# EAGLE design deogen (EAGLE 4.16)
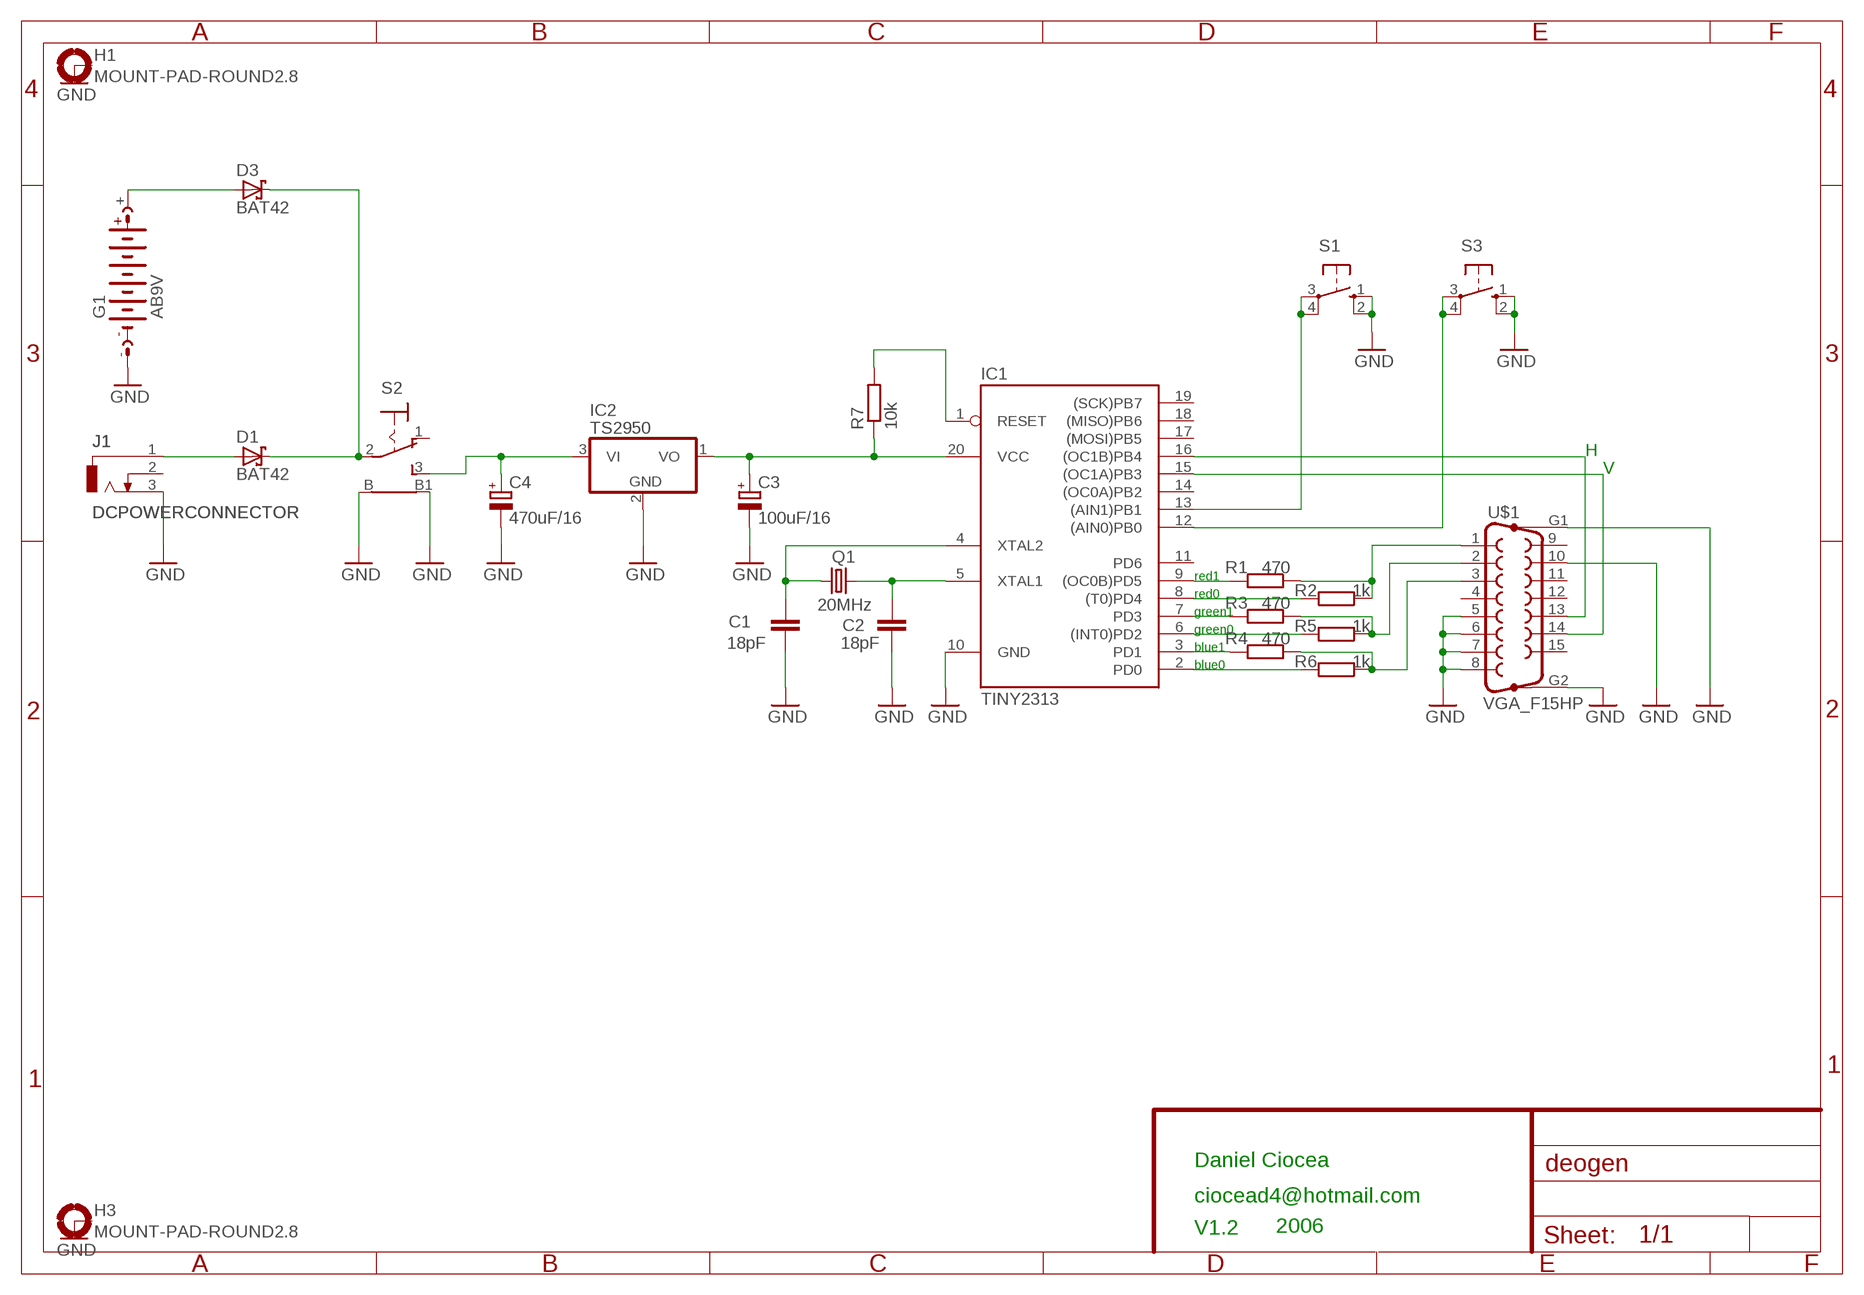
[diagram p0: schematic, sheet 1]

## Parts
C1  18pF  C-EU025-024X044  [C025-024X044]
C2  18pF  C-EU025-024X044  [C025-024X044]
C3  100uF/16  CPOL-EUE2.5-6  [E2,5-6]
C4  470uF/16  CPOL-EUE3.5-8  [E3,5-8]
D1  BAT42  [DO35-10]
D3  BAT42  [DO35-10]
G1  AB9V  [AB9V]
H1  MOUNT-PAD-ROUND2.8  [2,8-PAD]
H3  MOUNT-PAD-ROUND2.8  [2,8-PAD]
IC1  TINY2313  [DIL20]
IC2  TS2950  LINEAR_78L  [TO92]
J1  DCPOWERCONNECTOR  [DC_POWER_JACK]
Q1  20MHz  CRYTALHC49S  [HC49/S]
R1  470  R-EU_0207/7  [0207/7]
R2  1k  R-EU_0207/7  [0207/7]
R3  470  R-EU_0207/7  [0207/7]
R4  470  R-EU_0207/7  [0207/7]
R5  1k  R-EU_0207/7  [0207/7]
R6  1k  R-EU_0207/7  [0207/7]
R7  10k  R-EU_0207/7  [0207/7]
S1  10-XX  [B3F-10XX]
S2  9070-1W  [9070-1W]
S3  10-XX  [B3F-10XX]
U$1  VGA_F15HP  [F15]

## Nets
GND: C1.2 C2.2 C3.- C4.- G1.- H1.B2,8(MOUNT) H3.B2,8(MOUNT) IC1.10(GND) IC2.2(GND) J1.3 S1.1(S) S1.2(S1) S2.B S2.B1 S3.1(S) S3.2(S1) U$1.5 U$1.6 U$1.7 U$1.8 U$1.10 U$1.G1 U$1.G2
N$1: IC1.2(PD0) R6.2
N$2: IC1.3(PD1) R4.2
N$3: IC1.6((INT0)PD2) R5.2
N$4: IC1.7(PD3) R3.2
N$5: IC1.8((T0)PD4) R2.2
N$6: IC1.9((OC0B)PD5) R1.2
N$7: R1.1 R2.1 U$1.1
N$8: R3.1 R5.1 U$1.2
N$9: R4.1 R6.1 U$1.3
N$10: C1.1 IC1.4(XTAL2) Q1.1
N$11: C2.1 IC1.5(XTAL1) Q1.2
N$12: IC1.16((OC1B)PB4) U$1.13
N$13: IC1.15((OC1A)PB3) U$1.14
N$14: D1.C D3.C S2.2(P)
N$15: D1.A J1.1
N$16: IC1.13((AIN1)PB1) S1.3(P) S1.4(P1)
N$17: IC1.12((AIN0)PB0) S3.3(P) S3.4(P1)
N$19: IC1.1(RESET) R7.2
N$22: D3.A G1.+
N$23: C3.+ IC1.20(VCC) IC2.1(VO) R7.1
N$24: C4.+ IC2.3(VI) S2.3(S)
Unconnected: IC1.11(PD6) IC1.14((OC0A)PB2) IC1.17((MOSI)PB5) IC1.18((MISO)PB6) IC1.19((SCK)PB7) J1.2 S2.1(O) U$1.4 U$1.9 U$1.11 U$1.12 U$1.15

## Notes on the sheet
- H
- V
- red1
- red0
- green1
- green0
- blue1
- blue0
- Daniel Ciocea
- ciocead4@hotmail.com
- V1.2 | 2006

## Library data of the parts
C1 C2 = rcl:C-EU: CAPACITOR, European symbol
C3 C4 = rcl:CPOL-EU: POLARIZED CAPACITOR, European symbol
D1 D3 = diode:BAT42: DIODE
G1 = battery:AB9V: 9-V BATTERY CLIP
H1 H3 = holes:MOUNT-PAD-ROUND: MOUNTING PAD, round
IC1 = atmel:TINY2313*
IC2 = deogen:LINEAR_78*: Positive VOLTAGE REGULATOR Source: http://cache.national.com/ds/LM/LM78L05.pdf http://www.fairchildsemi.com/ds/LM/LM7805.pdf
J1 = deogen:DCPOWERCONNECTOR: DC POWER JACK Source: DCJ0202.pdf
Q1 = crystal:CRYTAL: CRYSTAL
R1-R7 = rcl:R-EU_: RESISTOR, European symbol
S1 S3 = switch-omron:10-XX: OMRON SWITCH
S2 = switch:9070-1W: TOGGLE SWITCH Marquardt
U$1 = deogen:VGA_F15HP

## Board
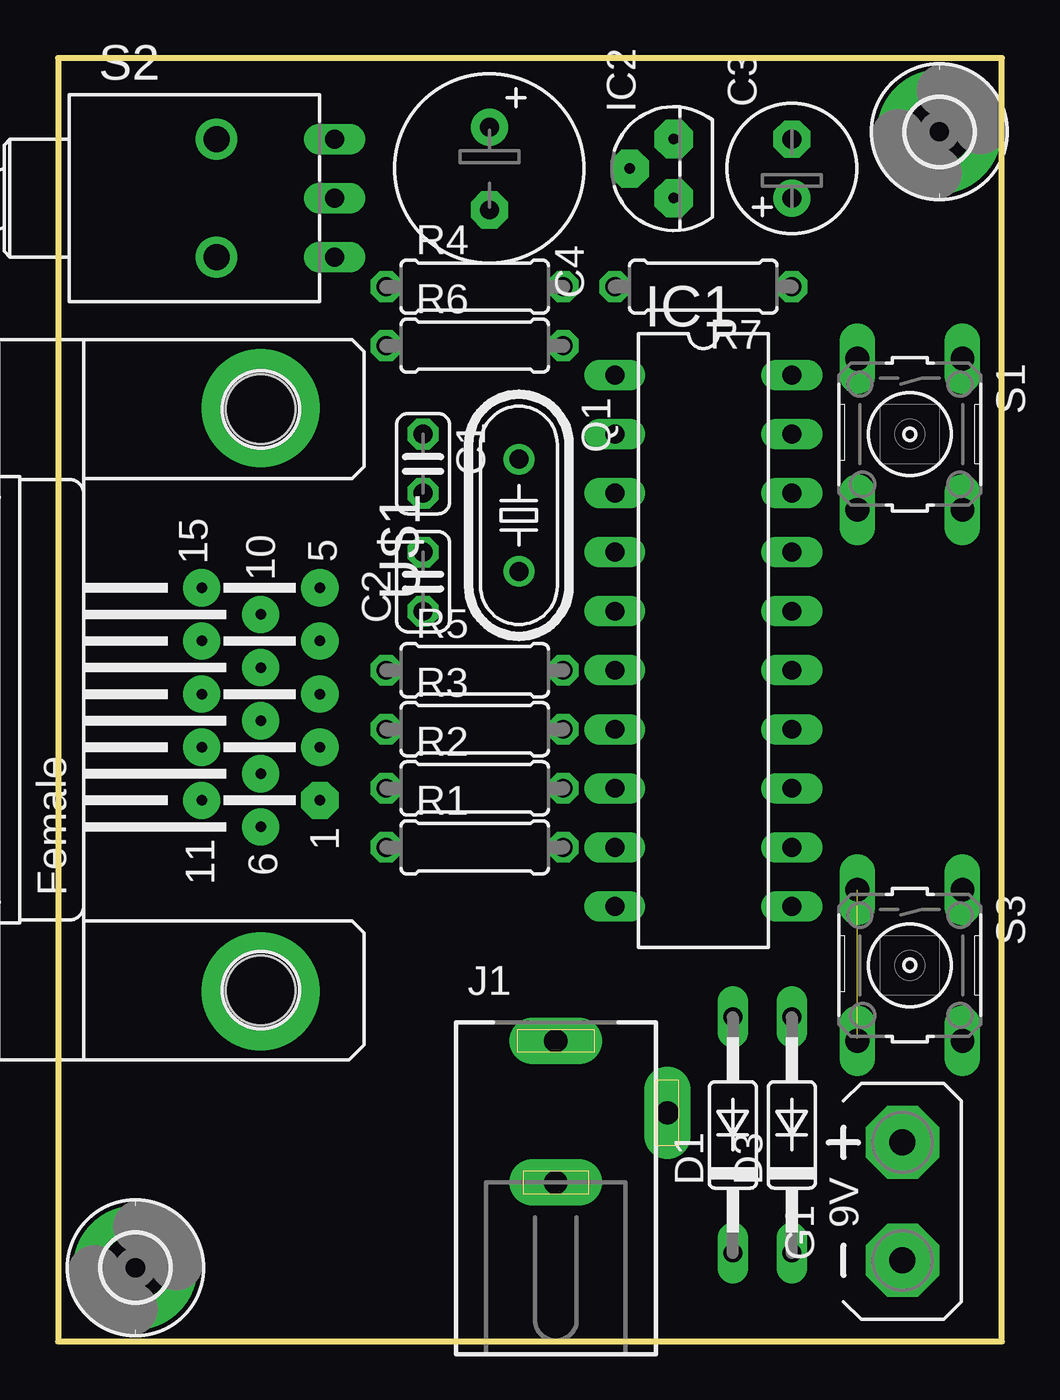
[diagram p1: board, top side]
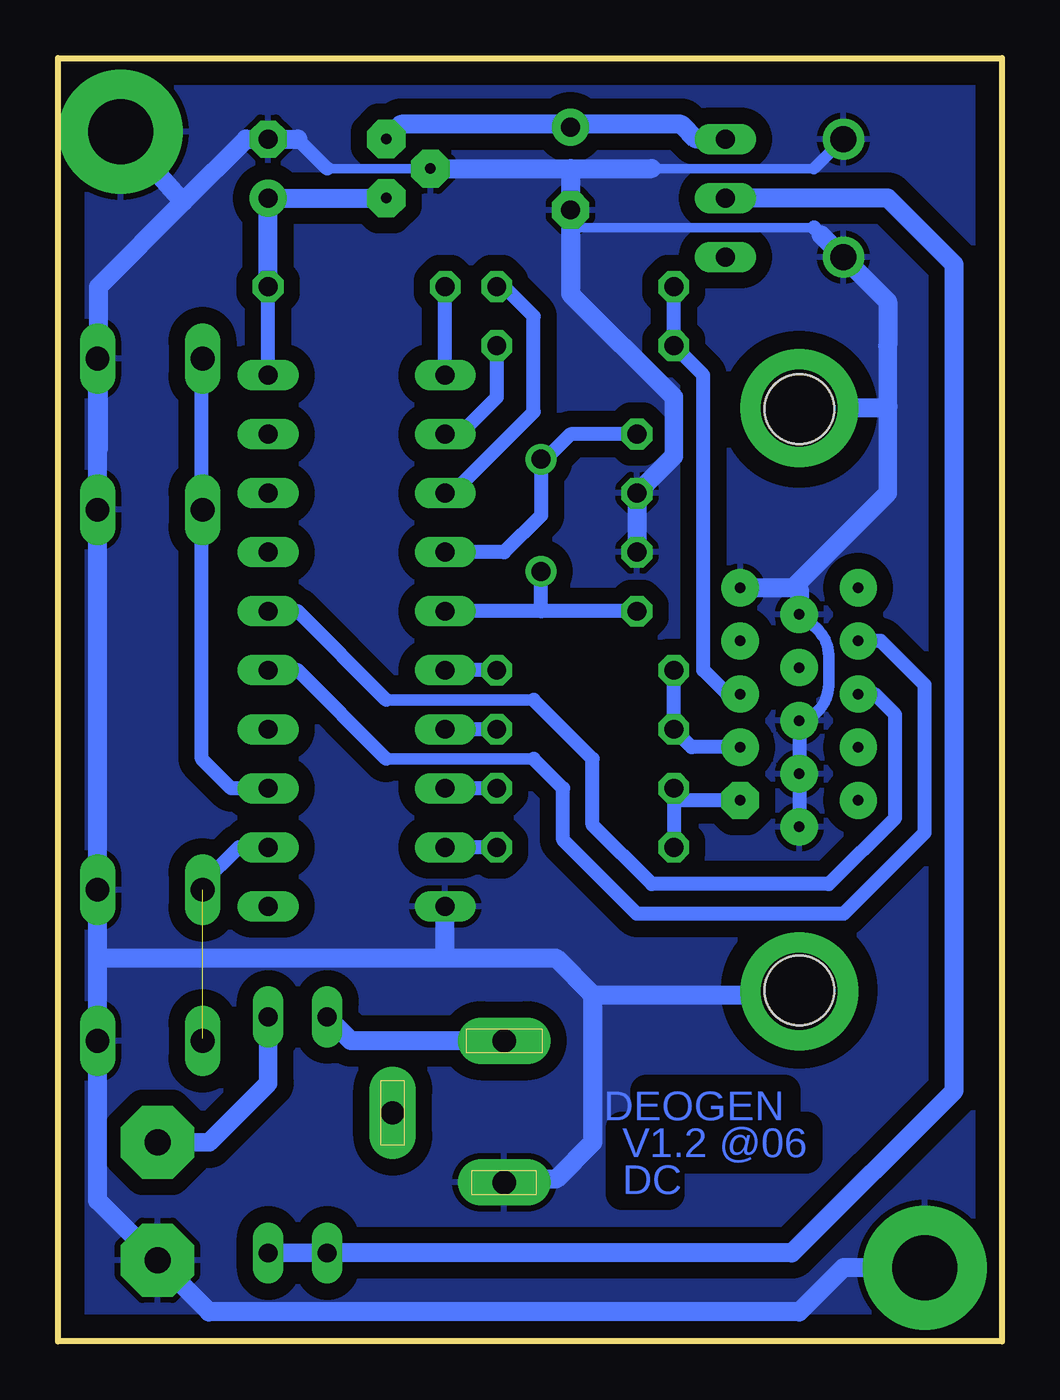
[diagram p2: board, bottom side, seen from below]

Size 40.63 x 55.23 mm. Coordinates in mm from the lower left corner, seen from the top.
Outline: 0,0 40.63,0 40.63,55.23 0,55.23 0,0
Copper layers (1*16): Top 0.035mm / dielectric 1.5mm / Bottom 0.035mm
Design rules "default": minimum track width 10mil, minimum drill 0.0102mm, track to track 8mil, track to pad 8mil, pad to pad 8mil, via to via 8mil, smd to smd 8mil, copper to edge 40mil, drill to drill 8mil, minimum pad ring 10mil, minimum via ring 8mil, stop-mask expansion 4mil, vias tented up to drill 0mil, thermal gap 10mil

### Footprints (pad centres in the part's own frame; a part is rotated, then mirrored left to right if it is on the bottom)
C025-024X044 = drill 0.813 octagon: 1 -1.27,0; 2 1.27,0
E2,5-6 = drill 0.813 pad 1.6 round: + -1.27,0 | drill 0.813 pad 1.6 octagon: - 1.27,0
E3,5-8 = drill 0.813 pad 1.6 round: + -1.778,0 | drill 0.813 pad 1.6 octagon: - 1.778,0
DO35-10 = drill 0.813 long: A 5.08,0; C -5.08,0
AB9V = drill 1.118 pad 3.15 octagon: + 0,2.54; - 0,-2.54
2,8-PAD = drill 2.8 pad 5.334 round: B2,8 0,0
DIL20 = drill 0.813 long: 1 -11.43,-3.81; 2 -8.89,-3.81; 3 -6.35,-3.81; 4 -3.81,-3.81; 5 -1.27,-3.81; 6 1.27,-3.81; 7 3.81,-3.81; 8 6.35,-3.81; 9 8.89,-3.81; 10 11.43,-3.81; 11 11.43,3.81; 12 8.89,3.81; 13 6.35,3.81; 14 3.81,3.81; 15 1.27,3.81; 16 -1.27,3.81; 17 -3.81,3.81; 18 -6.35,3.81; 19 -8.89,3.81; 20 -11.43,3.81
TO92 = drill 0.45 pad 1.65 octagon: 1 -1.27,0; 2 0,1.905; 3 1.27,0
DC_POWER_JACK = drill 1 pad 2 long: 1 0,3.1; 2 4.8,0; 3 0,-3
HC49/S = drill 0.813 round: 1 -2.413,0; 2 2.413,0
0207/7 = drill 0.813 octagon: 1 -3.81,0; 2 3.81,0
B3F-10XX = drill 1.016 long: 1 -3.251,2.261; 2 3.251,2.261; 3 -3.251,-2.261; 4 3.251,-2.261
9070-1W = drill 0.813 long: 1 5.08,-2.54; 2 5.08,0; 3 5.08,2.54 | drill 1.118 pad 1.778 round: B 0,-2.54; B1 0,2.54
F15 = drill 0.45 pad 1.6 octagon: 1 4.329,7.62 | drill 0.45 pad 1.6 round: 2 2.043,7.62; 3 -0.243,7.62; 4 -2.529,7.62; 5 -4.815,7.62; 6 5.472,5.08; 7 3.186,5.08; 8 0.9,5.08; 9 -1.386,5.08; 10 -3.672,5.08; 11 4.329,2.54; 12 2.043,2.54; 13 -0.243,2.54; 14 -2.529,2.54; 15 -4.815,2.54 | drill 3.302 pad 5.08 round: G1 12.548,5.08; G2 -12.548,5.08 | hole 3: -12.5,5.08; 12.5,5.08

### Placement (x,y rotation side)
C1  15.71,37.78 270 top
C2  15.71,32.7 90 top
C3  31.59,50.48 90 top
C4  18.57,50.48 270 top
D1  29.05,8.88 90 top
D3  31.59,8.88 90 top
G1  36.35,6.03 0 top
H1  37.94,52.07 0 top
H3  3.33,3.17 0 top
IC1  27.78,30.16 270 top
IC2  26.51,50.48 90 top
J1  21.43,9.84 0 top
Q1  19.84,35.55 270 top
R1  17.93,21.27 0 top
R2  17.93,23.81 0 top
R3  17.93,26.35 0 top
R4  17.93,45.4 0 top
R5  17.93,28.89 0 top
R6  17.93,42.86 0 top
R7  27.78,45.4 180 top
S1  36.66,39.05 270 top
S2  6.82,49.21 0 top
S3  36.66,16.19 270 top
U$1  3.65,27.62 270 top

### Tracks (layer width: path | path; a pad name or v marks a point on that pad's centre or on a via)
GND
  Bottom 0.406: S1.2 38.93,32.02 38.89,32.06 38.93,32.1 | S3.1 38.93,21.94 38.89,21.9 | 38.89,38.41 38.93,38.45 S1.1 | S3.2 38.93,12.97 38.89,13.01 38.93,13.05 | U$1.6 8.73,21.9 | 8.73,26.98 U$1.8 8.73,26.67 | 29.05,50.48 IC2.2 | 18.57,47.94 8.09,47.94 | 15.08,50.48 8.09,50.48
  Bottom 0.5: 8.73,26.67 arc-75 7.46,28.25 arc-2 7.46,29.52 arc-51 8.09,30.79 8.73,31.43 | 8.09,50.48 S2.B1
  Bottom 0.61: 8.73,26.67 U$1.7 U$1.6 | 30.32,51.75 29.05,50.48 | 8.09,47.94 7.77,47.62
  Bottom 0.8: 4.92,42.86 4.92,40.32 4.92,36.51 8.73,32.7 | 14.12,40.64 14.12,38.09
  Bottom 0.813: 38.93,32.1 S1.1 | S1.2 S3.1 38.93,16.51 | 38.93,13.05 38.93,16.51 | S3.2 38.93,6.07 G1.- 34.12,1.26 8.73,1.26 6.82,3.17 H3.B2,8 | C2.2 C1.2 14.12,38.09 | 11.21,32.43 8.99,32.43 8.88,32.54 | 8.73,32.7 8.88,32.54 | 8.88,32.54 8.73,32.38 8.73,31.43 U$1.10 | 8.88,32.54 | U$1.G2 4.92,40.17 4.92,40.32 | 23.96,16.51 IC1.10 | 38.93,16.51 23.96,16.51 | J1.3 21.43,6.98 19.2,6.98 17.62,8.57 17.62,14.92 | 4.92,42.86 4.92,44.76 S2.B 7.77,47.62 | 35.24,49.05 38.89,45.4 38.89,38.41 | 35.24,49.05 32.54,51.75 C3.- 30.32,51.75 | 14.12,40.64 18.57,45.08 18.57,47.94 C4.- 18.57,50.48 | IC2.2 18.57,50.48 | 35.24,49.05 35.4,49.21 H1.B2,8 | 17.62,14.92 19.2,16.51 23.96,16.51 | U$1.G1 8.73,14.92 17.62,14.92 | 18.57,50.48 15.08,50.48
  pour Bottom (isolate 0.7): -0.17,55.56 40.79,55.56 40.79,-0.32 -0.17,-0.32
N$1
  Bottom 0.6: R6.2 21.74,40.64 23.33,39.05 IC1.2
N$2
  Bottom 0.6: R4.2 21.43,45.4 20.16,44.13 20.16,40 23.65,36.51 IC1.3
N$3
  Bottom 0.6: R5.2 IC1.6
N$4
  Bottom 0.6: R3.2 IC1.7
N$5
  Bottom 0.6: R2.2 IC1.8
N$6
  Bottom 0.6: R1.2 IC1.9
N$7
  Bottom 0.6: 14.12,23.49 R1.1
  Bottom 0.61: R2.1 14.12,23.49 13.92,23.29 U$1.1
N$8
  Bottom 0.6: R5.1 13.81,28.89 14.12,28.57 R3.1 13.49,25.71
  Bottom 0.61: U$1.2 13.35,25.57 13.49,25.71
N$9
  Bottom 0.406: 11.83,27.86 11.34,27.86 11.27,27.94 U$1.3
  Bottom 0.61: R4.1 R6.1 12.85,41.59 12.85,33.65 12.85,30.16 12.85,28.89 11.83,27.86
N$10
  Bottom 0.6: IC1.4 21.43,33.97 19.84,35.55 Q1.1 19.84,37.78 18.57,39.05
  Bottom 0.61: C1.1 18.57,39.05
N$11
  Bottom 0.6: IC1.5 19.84,31.43 Q1.2
  Bottom 0.61: C2.1 19.84,31.43
N$12
  Bottom 0.406: U$1.13 6.18,27.94 6.11,27.86
  Bottom 0.5: 20.16,27.62 26.51,27.62
  Bottom 0.61: IC1.16 30.32,31.43 26.51,27.62 | 20.16,27.62 17.62,25.08 17.62,22.22 15.08,19.68 7.46,19.68 4.6,22.54 4.6,26.98 5.48,27.86 6.11,27.86
N$13
  Bottom 0.406: U$1.14
  Bottom 0.5: 20.16,25.08 26.51,25.08
  Bottom 0.61: 20.16,25.08 18.89,23.81 18.89,21.58 15.71,18.41 6.82,18.41 3.33,21.9 3.33,28.25 5.22,30.15 U$1.14 | 26.51,25.08 30.32,28.89 IC1.15
N$14
  Bottom 0.8: D1.C D3.C
  Bottom 0.813: D1.C 9.04,3.81 2.06,10.79 2.06,46.35 4.92,49.21 S2.2
N$15
  Bottom 0.813: D1.A 28.02,12.94 21.5,12.94 21.43,13.01 J1.1
N$16
  Bottom 0.406: 34.4,42.26 S1.3
  Bottom 0.61: 34.4,42.26 34.44,42.22 34.44,35.83 | S1.4 34.44,35.76 34.44,25.08 33.17,23.81 IC1.13
  Bottom 0.813: 34.44,42.22 34.44,42.26 S1.3 | S1.4 34.44,35.83
N$17  (1 unrouted)
  Bottom 0.406: 34.4,19.72 34.4,20 34.12,20 34.4,19.72 | S3.3 34.4,19.72
  Bottom 0.61: IC1.12 32.86,21.27 34.44,19.68 34.4,19.64 S3.3 | S3.4 34.4,12.97 34.44,13.01 34.4,13.05
N$19
  Bottom 0.61: IC1.1 R7.2
N$22
  Bottom 0.8: D3.A 31.59,11.11 34.12,8.57 G1.+
N$23
  Bottom 0.61: IC1.20 R7.1
  Bottom 0.813: R7.1 C3.+ IC2.1
N$24
  Bottom 0.813: S2.3 13.17,51.75 13.81,52.38 18.57,52.38 | 18.57,52.38 C4.+ | IC2.3 25.87,52.38 18.57,52.38

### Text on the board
Bottom: DEOGEN | V1.2 @06 | DC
